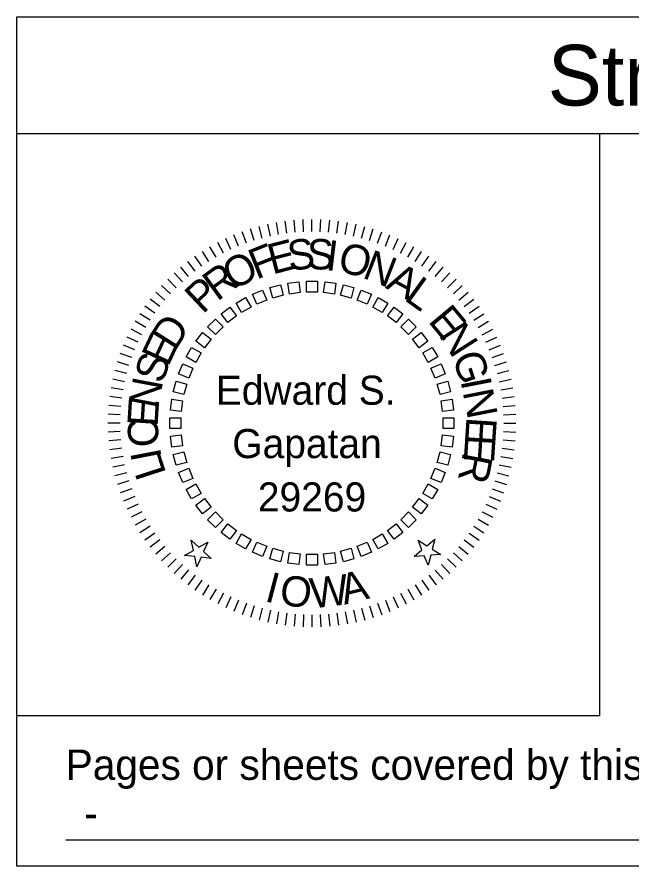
# Model space of a CAD drawing. Extents: x -0.84 to 4.97, y -1.01 to 2.42.
# Drawn here: x 2.9797 to 3.1904, y -0.6532 to -0.3615 of the extents above; entities that cross this region are included whole.
import ezdxf

# ---------------------------------------------------------------- set-up
doc = ezdxf.new("R2010")
doc.units = 0
for name, color, linetype in [('Level 1', 7, 'Continuous'), ('Level 2', 7, 'Continuous'), ('SheetGridMajor', 7, 'Continuous'), ('SheetGridMinor', 7, 'Continuous'), ('SheetText', 7, 'Continuous')]:
    doc.layers.add(name, color=color, linetype=linetype)

msp = doc.modelspace()

# ---------------------------------------------------------------- linework, layer by layer
at = {"layer": 'Level 1'}
for p, q in [((3.07231, -0.43576), (3.07177, -0.43163)), ((3.07517, -0.43545), (3.0748, -0.4313)), ((3.07803, -0.43526), (3.07785, -0.4311)), ((3.08091, -0.4352), (3.08091, -0.43103)), ((3.08378, -0.43526), (3.08396, -0.4311)), ((3.08664, -0.43545), (3.08701, -0.4313)), ((3.0895, -0.43576), (3.09004, -0.43163)), ((3.06111, -0.43825), (3.05986, -0.43427)), ((3.06387, -0.43744), (3.06279, -0.43342)), ((3.06666, -0.43676), (3.06575, -0.43269)), ((3.06947, -0.4362), (3.06875, -0.4321)), ((3.09234, -0.4362), (3.09306, -0.4321)), ((3.09515, -0.43676), (3.09606, -0.43269)), ((3.09794, -0.43744), (3.09902, -0.43342)), ((3.1007, -0.43825), (3.10195, -0.43427)), ((3.05571, -0.44021), (3.05412, -0.43636)), ((3.05839, -0.43917), (3.05696, -0.43526)), ((3.10342, -0.43917), (3.10485, -0.43526)), ((3.1061, -0.44021), (3.10769, -0.43636)), ((3.04799, -0.44402), (3.04591, -0.44041)), ((3.05051, -0.44264), (3.04858, -0.43894)), ((3.05308, -0.44137), (3.05132, -0.43759)), ((3.10873, -0.44137), (3.11049, -0.43759)), ((3.1113, -0.44264), (3.11323, -0.43894)), ((3.11382, -0.44402), (3.1159, -0.44041)), ((3.04553, -0.44551), (3.04329, -0.442)), ((3.11628, -0.44551), (3.11852, -0.442)), ((3.04083, -0.4488), (3.03829, -0.4455)), ((3.04314, -0.44711), (3.04076, -0.44369)), ((3.11867, -0.44711), (3.12105, -0.44369)), ((3.12098, -0.44881), (3.12352, -0.4455)), ((3.03859, -0.4506), (3.03591, -0.44741)), ((3.12322, -0.4506), (3.1259, -0.44741)), ((3.03435, -0.45448), (3.03141, -0.45154)), ((3.03643, -0.4525), (3.03361, -0.44942)), ((3.12538, -0.4525), (3.1282, -0.44943)), ((3.12746, -0.45448), (3.1304, -0.45154)), ((3.03237, -0.45656), (3.0293, -0.45374)), ((3.12944, -0.45656), (3.13251, -0.45374)), ((3.03047, -0.45872), (3.02728, -0.45604)), ((3.13134, -0.45872), (3.13453, -0.45604)), ((3.02868, -0.46096), (3.02537, -0.45842)), ((3.13313, -0.46096), (3.13644, -0.45842)), ((3.02538, -0.46566), (3.02187, -0.46342)), ((3.02698, -0.46327), (3.02356, -0.46088)), ((3.13483, -0.46327), (3.13825, -0.46088)), ((3.13643, -0.46566), (3.13994, -0.46342)), ((3.02389, -0.46812), (3.02028, -0.46603)), ((3.13792, -0.46812), (3.14153, -0.46603)), ((3.02251, -0.47064), (3.01881, -0.46871)), ((3.1393, -0.47064), (3.143, -0.46871)), ((3.02124, -0.47321), (3.01746, -0.47145)), ((3.14057, -0.47321), (3.14435, -0.47145)), ((3.02008, -0.47584), (3.01623, -0.47425)), ((3.14173, -0.47584), (3.14558, -0.47425)), ((3.01904, -0.47852), (3.01513, -0.47709)), ((3.14277, -0.47852), (3.14668, -0.47709)), ((3.01812, -0.48124), (3.01415, -0.47998)), ((3.14369, -0.48124), (3.14766, -0.47999)), ((3.01732, -0.48399), (3.01329, -0.48292)), ((3.14449, -0.484), (3.14852, -0.48292)), ((3.01663, -0.48678), (3.01256, -0.48588)), ((3.14518, -0.48679), (3.14925, -0.48588)), ((3.01607, -0.4896), (3.01197, -0.48888)), ((3.14574, -0.4896), (3.14984, -0.48888)), ((3.01564, -0.49244), (3.0115, -0.4919)), ((3.14617, -0.49244), (3.15031, -0.4919)), ((3.01532, -0.4953), (3.01117, -0.49493)), ((3.14649, -0.4953), (3.15064, -0.49493)), ((3.01513, -0.49816), (3.01097, -0.49798)), ((3.14668, -0.49816), (3.15084, -0.49798)), ((3.01507, -0.50103), (3.0109, -0.50103)), ((3.14674, -0.50103), (3.1509, -0.50103)), ((3.01513, -0.5039), (3.01097, -0.50409)), ((3.14667, -0.50391), (3.15084, -0.50409)), ((3.01532, -0.50677), (3.01117, -0.50713)), ((3.14649, -0.50677), (3.15064, -0.50714)), ((3.01563, -0.50963), (3.0115, -0.51017)), ((3.14617, -0.50963), (3.15031, -0.51017)), ((3.01607, -0.51247), (3.01197, -0.51319)), ((3.14574, -0.51247), (3.14984, -0.51319)), ((3.01663, -0.51528), (3.01256, -0.51618)), ((3.14518, -0.51528), (3.14924, -0.51618)), ((3.01732, -0.51807), (3.01329, -0.51915)), ((3.14449, -0.51807), (3.14852, -0.51915)), ((3.01812, -0.52083), (3.01414, -0.52208)), ((3.14369, -0.52083), (3.14766, -0.52208)), ((3.01904, -0.52355), (3.01513, -0.52497)), ((3.14277, -0.52355), (3.14668, -0.52498)), ((3.02008, -0.52623), (3.01623, -0.52782)), ((3.14173, -0.52623), (3.14558, -0.52782)), ((3.02124, -0.52886), (3.01746, -0.53062)), ((3.14057, -0.52886), (3.14435, -0.53062)), ((3.02251, -0.53143), (3.01881, -0.53336)), ((3.1393, -0.53143), (3.14299, -0.53336)), ((3.02389, -0.53395), (3.02028, -0.53603)), ((3.02538, -0.53641), (3.02187, -0.53864)), ((3.13643, -0.53641), (3.13994, -0.53864)), ((3.13792, -0.53395), (3.14153, -0.53603)), ((3.02698, -0.53879), (3.02356, -0.54118)), ((3.13483, -0.53879), (3.13824, -0.54118)), ((3.02868, -0.54111), (3.02537, -0.54365)), ((3.13313, -0.54111), (3.13644, -0.54365)), ((3.03047, -0.54335), (3.02728, -0.54603)), ((3.13134, -0.54335), (3.13453, -0.54603)), ((3.03237, -0.54551), (3.02929, -0.54832)), ((3.03435, -0.54758), (3.03141, -0.55053)), ((3.12746, -0.54759), (3.1304, -0.55053)), ((3.12944, -0.54551), (3.13251, -0.54833)), ((3.03643, -0.54957), (3.03361, -0.55264)), ((3.12538, -0.54957), (3.12819, -0.55264)), ((3.03859, -0.55146), (3.03591, -0.55466)), ((3.04083, -0.55326), (3.03829, -0.55657)), ((3.12098, -0.55326), (3.12352, -0.55657)), ((3.12322, -0.55147), (3.1259, -0.55466)), ((3.04314, -0.55496), (3.04075, -0.55837)), ((3.04553, -0.55656), (3.04329, -0.56007)), ((3.11628, -0.55656), (3.11851, -0.56007)), ((3.11866, -0.55496), (3.12105, -0.55837)), ((3.04799, -0.55805), (3.0459, -0.56165)), ((3.05051, -0.55943), (3.04858, -0.56312)), ((3.1113, -0.55943), (3.11323, -0.56312)), ((3.11382, -0.55805), (3.1159, -0.56166)), ((3.05308, -0.5607), (3.05132, -0.56447)), ((3.05571, -0.56186), (3.05412, -0.5657)), ((3.05839, -0.5629), (3.05696, -0.56681)), ((3.10342, -0.5629), (3.10485, -0.56681)), ((3.1061, -0.56186), (3.10769, -0.56571)), ((3.10873, -0.5607), (3.11049, -0.56448)), ((3.06111, -0.56382), (3.05985, -0.56779)), ((3.06387, -0.56462), (3.06279, -0.56865)), ((3.06666, -0.56531), (3.06575, -0.56937)), ((3.09515, -0.56531), (3.09605, -0.56937)), ((3.09794, -0.56462), (3.09902, -0.56865)), ((3.1007, -0.56382), (3.10195, -0.56779)), ((3.06947, -0.56587), (3.06875, -0.56997)), ((3.07231, -0.5663), (3.07177, -0.57043)), ((3.07517, -0.56662), (3.0748, -0.57077)), ((3.07803, -0.5668), (3.07785, -0.57097)), ((3.0809, -0.56687), (3.0809, -0.57103)), ((3.08378, -0.5668), (3.08396, -0.57097)), ((3.08664, -0.56662), (3.08701, -0.57077)), ((3.0895, -0.5663), (3.09004, -0.57043)), ((3.09234, -0.56587), (3.09306, -0.56997))]:
    msp.add_line(p, q, dxfattribs=at)
for points in [[(3.07107, -0.45708), (3.06745, -0.45805), (3.06648, -0.45443), (3.0701, -0.45346)], [(3.07689, -0.45617), (3.07317, -0.45666), (3.07268, -0.45295), (3.0764, -0.45246)], [(3.08278, -0.45603), (3.07903, -0.45603), (3.07903, -0.45228), (3.08278, -0.45228)], [(3.08864, -0.45666), (3.08492, -0.45617), (3.08541, -0.45246), (3.08913, -0.45295)], [(3.09436, -0.45805), (3.09074, -0.45708), (3.09171, -0.45346), (3.09533, -0.45443)], [(3.06003, -0.46112), (3.05678, -0.463), (3.05491, -0.45975), (3.05815, -0.45788)], [(3.06542, -0.45874), (3.06195, -0.46018), (3.06052, -0.45671), (3.06398, -0.45528)], [(3.09986, -0.46018), (3.09639, -0.45874), (3.09783, -0.45528), (3.10129, -0.45671)], [(3.10503, -0.463), (3.10178, -0.46113), (3.10366, -0.45788), (3.1069, -0.45975)], [(3.055, -0.46419), (3.05202, -0.46647), (3.04974, -0.4635), (3.05271, -0.46122)], [(3.10979, -0.46647), (3.10681, -0.46419), (3.10909, -0.46122), (3.11207, -0.4635)], [(3.05041, -0.46789), (3.04776, -0.47054), (3.04511, -0.46789), (3.04776, -0.46524)], [(3.11405, -0.47054), (3.1114, -0.46789), (3.11405, -0.46524), (3.1167, -0.46789)], [(3.04634, -0.47215), (3.04406, -0.47513), (3.04109, -0.47284), (3.04337, -0.46987)], [(3.11775, -0.47513), (3.11546, -0.47215), (3.11844, -0.46987), (3.12072, -0.47284)], [(3.04287, -0.47691), (3.041, -0.48016), (3.03775, -0.47828), (3.03962, -0.47504)], [(3.12081, -0.48016), (3.11894, -0.47691), (3.12219, -0.47503), (3.12406, -0.47828)], [(3.04005, -0.48208), (3.03861, -0.48555), (3.03515, -0.48411), (3.03658, -0.48065)], [(3.1232, -0.48555), (3.12176, -0.48208), (3.12523, -0.48065), (3.12666, -0.48411)], [(3.03792, -0.48758), (3.03695, -0.4912), (3.03333, -0.49023), (3.0343, -0.48661)], [(3.12486, -0.4912), (3.12389, -0.48758), (3.12751, -0.4866), (3.12848, -0.49023)], [(3.03653, -0.4933), (3.03605, -0.49702), (3.03233, -0.49653), (3.03282, -0.49281)], [(3.12576, -0.49702), (3.12527, -0.4933), (3.12899, -0.49281), (3.12948, -0.49653)], [(3.0359, -0.49916), (3.0359, -0.50291), (3.03215, -0.50291), (3.03215, -0.49916)], [(3.1259, -0.50291), (3.1259, -0.49916), (3.12965, -0.49916), (3.12965, -0.50291)], [(3.03604, -0.50505), (3.03653, -0.50877), (3.03282, -0.50926), (3.03233, -0.50554)], [(3.12528, -0.50877), (3.12576, -0.50505), (3.12948, -0.50554), (3.12899, -0.50926)], [(3.03695, -0.51087), (3.03792, -0.51449), (3.0343, -0.51546), (3.03333, -0.51184)], [(3.12389, -0.51449), (3.12486, -0.51087), (3.12848, -0.51184), (3.12751, -0.51546)], [(3.03861, -0.51652), (3.04005, -0.51999), (3.03658, -0.52142), (3.03515, -0.51796)], [(3.12176, -0.51999), (3.1232, -0.51652), (3.12666, -0.51796), (3.12523, -0.52142)], [(3.041, -0.52191), (3.04287, -0.52516), (3.03962, -0.52703), (3.03775, -0.52379)], [(3.11894, -0.52516), (3.12081, -0.52191), (3.12406, -0.52379), (3.12219, -0.52703)], [(3.04406, -0.52694), (3.04635, -0.52992), (3.04337, -0.5322), (3.04109, -0.52922)], [(3.11546, -0.52992), (3.11775, -0.52694), (3.12072, -0.52922), (3.11844, -0.5322)], [(3.04776, -0.53153), (3.05041, -0.53418), (3.04776, -0.53683), (3.04511, -0.53418)], [(3.1114, -0.53418), (3.11405, -0.53153), (3.1167, -0.53418), (3.11405, -0.53683)], [(3.05202, -0.53559), (3.055, -0.53788), (3.05271, -0.54085), (3.04974, -0.53857)], [(3.10681, -0.53788), (3.10979, -0.53559), (3.11207, -0.53857), (3.10909, -0.54085)], [(3.05678, -0.53907), (3.06003, -0.54094), (3.05815, -0.54419), (3.05491, -0.54232)], [(3.10178, -0.54094), (3.10503, -0.53907), (3.1069, -0.54232), (3.10366, -0.54419)], [(3.03947, -0.54126), (3.0421, -0.54363), (3.04518, -0.54186), (3.04373, -0.5451), (3.04637, -0.54747), (3.04284, -0.5471), (3.0414, -0.55034), (3.04066, -0.54687), (3.03714, -0.5465), (3.04021, -0.54473)], [(3.06195, -0.54189), (3.06542, -0.54333), (3.06398, -0.54679), (3.06052, -0.54536)], [(3.09639, -0.54333), (3.09986, -0.54189), (3.10129, -0.54536), (3.09783, -0.54679)], [(3.11732, -0.54124), (3.12033, -0.54312), (3.12304, -0.54085), (3.12219, -0.54429), (3.12519, -0.54616), (3.12166, -0.54641), (3.1208, -0.54985), (3.11947, -0.54656), (3.11593, -0.54681), (3.11865, -0.54453)], [(3.06745, -0.54402), (3.07107, -0.54499), (3.0701, -0.54861), (3.06648, -0.54764)], [(3.07317, -0.5454), (3.07689, -0.54589), (3.0764, -0.54961), (3.07268, -0.54912)], [(3.08492, -0.54589), (3.08864, -0.5454), (3.08913, -0.54912), (3.08541, -0.54961)], [(3.09074, -0.54499), (3.09436, -0.54401), (3.09533, -0.54764), (3.09171, -0.54861)], [(3.07903, -0.54603), (3.08278, -0.54603), (3.08278, -0.54978), (3.07903, -0.54978)]]:
    msp.add_lwpolyline(points, close=True, dxfattribs=at)
at = {"layer": 'SheetGridMajor'}
for p, q in [((2.97968, -0.40149), (3.60468, -0.40149)), ((3.17968, -0.60149), (3.17968, -0.40149)), ((2.97968, -0.60149), (3.17968, -0.60149))]:
    msp.add_line(p, q, dxfattribs=at)
msp.add_lwpolyline([(2.97968, -0.36149), (3.60468, -0.36149), (3.60468, -0.65315), (2.97968, -0.65315)], close=True, dxfattribs=at)
at = {"layer": 'SheetGridMinor'}
msp.add_line((2.9964, -0.64418), (3.58802, -0.64418), dxfattribs=at)

# ---------------------------------------------------------------- texts
at = {"layer": 'Level 1'}
for s, rotation, p in [('S', 7.3911, (3.07316, -0.44878)), ('F', 21.7736, (3.06185, -0.45178)), ('E', 14.5823, (3.06731, -0.45)), ('S', 0.1998, (3.07925, -0.44823)), ('I', 353.0085, (3.08536, -0.44837)), ('O', 345.8172, (3.0893, -0.44868)), ('O', 28.9649, (3.05392, -0.45561)), ('N', 338.6259, (3.09783, -0.45094)), ('R', 36.1562, (3.04838, -0.45939)), ('A', 331.4346, (3.10584, -0.45448)), ('P', 43.3475, (3.04342, -0.46379)), ('L', 324.2434, (3.11218, -0.45848)), ('E', 309.8608, (3.1205, -0.46605)), ('D', 57.7301, (3.03395, -0.47647)), ('N', 302.6695, (3.12421, -0.47074)), ('E', 64.9213, (3.03152, -0.48195)), ('S', 72.1126, (3.02968, -0.48779)), ('G', 288.2869, (3.12897, -0.47818)), ('N', 79.3039, (3.02803, -0.49642)), ('I', 281.0956, (3.13185, -0.48639)), ('N', 281.0956, (3.13261, -0.49025)), ('E', 86.4952, (3.02791, -0.50242)), ('C', 93.6865, (3.0285, -0.50899)), ('E', 266.2773, (3.13398, -0.49873)), ('E', 266.2773, (3.13359, -0.5047)), ('I', 100.8778, (3.0294, -0.51284)), ('L', 108.069, (3.03097, -0.51825)), ('R', 259.086, (3.13284, -0.51063)), ('I', 345.2906, (3.06434, -0.56206)), ('O', 352.4819, (3.06944, -0.5633)), ('W', 6.8645, (3.08084, -0.56473)), ('A', 14.0557, (3.09202, -0.56343))]:
    msp.add_text(s, height=0.01042, rotation=rotation, dxfattribs=at).set_placement(p)
at = {"layer": 'Level 2'}
for s, p in [('Edward S.', (3.04791, -0.4947)), ('Gapatan', (3.05356, -0.51303)), ('29269', (3.06235, -0.53136))]:
    msp.add_text(s, height=0.01, dxfattribs=at).set_placement(p)
at = {"layer": 'SheetText'}
for s, height, p in [('Structural Design', 0.0208333, (3.16182, -0.3919)), ('Pages or sheets covered by this seal:', 0.0104167, (2.9964, -0.62355)), ('-', 0.0104, (3.00277, -0.64015))]:
    msp.add_text(s, height=height, dxfattribs=at).set_placement(p)

doc.saveas('drawing.dxf')
